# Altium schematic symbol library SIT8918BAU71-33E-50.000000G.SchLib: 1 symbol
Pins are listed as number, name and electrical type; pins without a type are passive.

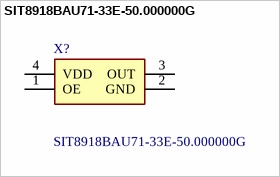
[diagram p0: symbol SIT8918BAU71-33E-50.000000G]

## SIT8918BAU71-33E-50.000000G
designator X?
Standard Clock Oscillators -40 to 125C, 2016, 20ppm, 'U' Drive Str, 3.3V, 50MHz, OE, 250 pcs T&R 8 mm; Manufacturer_Name: SiTime; Geometry.Height: 0.8mm
footprint SIT8918BAU7133E50000000G
pins: 1 OE, 2 GND, 3 OUT, 4 VDD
